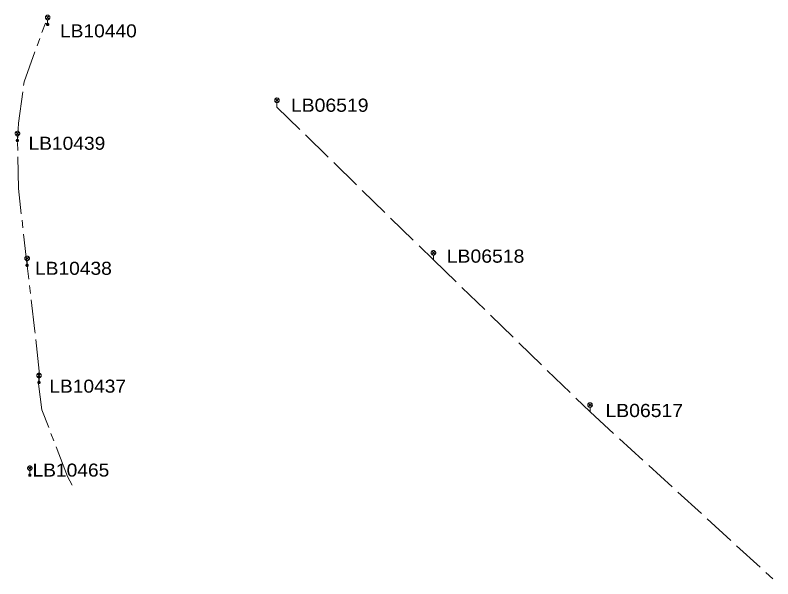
# Model space of a CAD drawing. Extents: x -691843 to -691118, y -976392 to -975793.
# Drawn here: x -691659.5 to -691534.9, y -976375.5 to -976282.7 of the extents above; entities that cross this region are included whole.
import ezdxf

# ---------------------------------------------------------------- set-up
doc = ezdxf.new("R2010")
doc.units = 0
doc.header["$LTSCALE"] = 0.87
doc.linetypes.add('LONG_DASH_SHORT_DASH', pattern=[9.9, 6, -1.2, 1.5, -1.2])
doc.linetypes.add('LONG_DASHED', pattern=[7.5, 6, -1.5])
doc.layers.add('1', color=7, linetype='Continuous', lineweight=13)

msp = doc.modelspace()

# ---------------------------------------------------------------- linework, layer by layer
at = {"layer": '1'}
for p, q in [((-691654.435, -976282.845), (-691653.905, -976283.375)), ((-691654.435, -976283.375), (-691653.905, -976282.845)), ((-691654.17, -976284.26), (-691654.17, -976283.485)), ((-691616.735, -976296.475), (-691616.205, -976297.005)), ((-691616.735, -976297.005), (-691616.205, -976296.475)), ((-691616.47, -976297.89), (-691616.47, -976297.115)), ((-691659.405, -976301.945), (-691658.875, -976302.475)), ((-691659.405, -976302.475), (-691658.875, -976301.945)), ((-691659.14, -976303.36), (-691659.14, -976302.585)), ((-691591.005, -976321.575), (-691590.475, -976322.105)), ((-691591.005, -976322.105), (-691590.475, -976321.575)), ((-691657.815, -976322.475), (-691657.285, -976323.005)), ((-691657.815, -976323.005), (-691657.285, -976322.475)), ((-691590.74, -976322.99), (-691590.74, -976322.215)), ((-691657.55, -976323.89), (-691657.55, -976323.115)), ((-691655.855, -976341.755), (-691655.325, -976342.285)), ((-691655.855, -976342.285), (-691655.325, -976341.755)), ((-691655.59, -976343.17), (-691655.59, -976342.395)), ((-691565.255, -976346.605), (-691564.725, -976347.135)), ((-691565.255, -976347.135), (-691564.725, -976346.605)), ((-691564.99, -976348.02), (-691564.99, -976347.245)), ((-691657.365, -976356.995), (-691656.835, -976357.525)), ((-691657.365, -976357.525), (-691656.835, -976356.995)), ((-691657.1, -976358.41), (-691657.1, -976357.635))]:
    msp.add_line(p, q, dxfattribs=at)
at = {"layer": '1', "linetype": 'LONG_DASH_SHORT_DASH'}
for p, q in [((-691654.54, -976284.04), (-691654.17, -976284.26)), ((-691654.54, -976284.04), (-691654.17, -976284.26)), ((-691654.54, -976284.04), (-691654.17, -976284.26)), ((-691654.54, -976284.04), (-691654.17, -976284.26)), ((-691654.54, -976284.04), (-691654.17, -976284.26)), ((-691654.54, -976284.04), (-691654.17, -976284.26)), ((-691654.54, -976284.04), (-691654.17, -976284.26)), ((-691659.11, -976303.48), (-691659.14, -976303.36)), ((-691659.11, -976303.48), (-691659.14, -976303.36)), ((-691659.11, -976303.48), (-691659.14, -976303.36)), ((-691659.11, -976303.48), (-691659.14, -976303.36)), ((-691659.11, -976303.48), (-691659.14, -976303.36)), ((-691659.11, -976303.48), (-691659.14, -976303.36)), ((-691659.11, -976303.48), (-691659.14, -976303.36)), ((-691659.11, -976303.48), (-691659.14, -976303.36)), ((-691657.53, -976323.97), (-691657.55, -976323.89)), ((-691657.53, -976323.97), (-691657.55, -976323.89)), ((-691657.53, -976323.97), (-691657.55, -976323.89)), ((-691657.53, -976323.97), (-691657.55, -976323.89)), ((-691657.53, -976323.97), (-691657.55, -976323.89)), ((-691657.53, -976323.97), (-691657.55, -976323.89)), ((-691657.53, -976323.97), (-691657.55, -976323.89)), ((-691657.53, -976323.97), (-691657.55, -976323.89)), ((-691655.67, -976343.36), (-691655.59, -976343.17)), ((-691655.67, -976343.36), (-691655.59, -976343.17)), ((-691655.67, -976343.36), (-691655.59, -976343.17)), ((-691655.67, -976343.36), (-691655.59, -976343.17)), ((-691655.67, -976343.36), (-691655.59, -976343.17)), ((-691655.67, -976343.36), (-691655.59, -976343.17)), ((-691655.67, -976343.36), (-691655.59, -976343.17)), ((-691655.67, -976343.36), (-691655.59, -976343.17))]:
    msp.add_line(p, q, dxfattribs=at)
at = {"layer": '1', "linetype": 'LONG_DASHED'}
for p, q in [((-691616.47, -976297.89), (-691590.74, -976322.99)), ((-691616.47, -976297.89), (-691590.74, -976322.99)), ((-691590.74, -976322.99), (-691564.99, -976348.02)), ((-691590.74, -976322.99), (-691564.99, -976348.02)), ((-691564.99, -976348.02), (-691534.94, -976375.47)), ((-691564.99, -976348.02), (-691534.94, -976375.47))]:
    msp.add_line(p, q, dxfattribs=at)
at = {"layer": '1'}
for points in [[(-691653.795, -976283.11), (-691653.801, -976283.045), (-691653.818, -976282.982), (-691653.845, -976282.923), (-691653.883, -976282.869), (-691653.929, -976282.823), (-691653.982, -976282.785), (-691654.042, -976282.758), (-691654.105, -976282.741), (-691654.17, -976282.735), (-691654.235, -976282.741), (-691654.298, -976282.758), (-691654.358, -976282.785), (-691654.411, -976282.823), (-691654.457, -976282.869), (-691654.495, -976282.923), (-691654.522, -976282.982), (-691654.539, -976283.045), (-691654.545, -976283.11), (-691654.539, -976283.175), (-691654.522, -976283.238), (-691654.495, -976283.298), (-691654.457, -976283.351), (-691654.411, -976283.397), (-691654.358, -976283.435), (-691654.298, -976283.462), (-691654.235, -976283.479), (-691654.17, -976283.485), (-691654.105, -976283.479), (-691654.042, -976283.462), (-691653.982, -976283.435), (-691653.929, -976283.397), (-691653.883, -976283.351), (-691653.845, -976283.298), (-691653.818, -976283.238), (-691653.801, -976283.175)], [(-691653.98, -976284.26), (-691653.983, -976284.227), (-691653.991, -976284.195), (-691654.005, -976284.165), (-691654.024, -976284.138), (-691654.048, -976284.114), (-691654.075, -976284.095), (-691654.105, -976284.081), (-691654.137, -976284.073), (-691654.17, -976284.07), (-691654.203, -976284.073), (-691654.235, -976284.081), (-691654.265, -976284.095), (-691654.292, -976284.114), (-691654.316, -976284.138), (-691654.335, -976284.165), (-691654.349, -976284.195), (-691654.357, -976284.227), (-691654.36, -976284.26), (-691654.357, -976284.293), (-691654.349, -976284.325), (-691654.335, -976284.355), (-691654.316, -976284.382), (-691654.292, -976284.406), (-691654.265, -976284.425), (-691654.235, -976284.439), (-691654.203, -976284.447), (-691654.17, -976284.45), (-691654.137, -976284.447), (-691654.105, -976284.439), (-691654.075, -976284.425), (-691654.048, -976284.406), (-691654.024, -976284.382), (-691654.005, -976284.355), (-691653.991, -976284.325), (-691653.983, -976284.293)], [(-691654.12, -976284.26), (-691654.121, -976284.251), (-691654.123, -976284.243), (-691654.127, -976284.235), (-691654.132, -976284.228), (-691654.138, -976284.222), (-691654.145, -976284.217), (-691654.153, -976284.213), (-691654.161, -976284.211), (-691654.17, -976284.21), (-691654.179, -976284.211), (-691654.187, -976284.213), (-691654.195, -976284.217), (-691654.202, -976284.222), (-691654.208, -976284.228), (-691654.213, -976284.235), (-691654.217, -976284.243), (-691654.219, -976284.251), (-691654.22, -976284.26), (-691654.219, -976284.269), (-691654.217, -976284.277), (-691654.213, -976284.285), (-691654.208, -976284.292), (-691654.202, -976284.298), (-691654.195, -976284.303), (-691654.187, -976284.307), (-691654.179, -976284.309), (-691654.17, -976284.31), (-691654.161, -976284.309), (-691654.153, -976284.307), (-691654.145, -976284.303), (-691654.138, -976284.298), (-691654.132, -976284.292), (-691654.127, -976284.285), (-691654.123, -976284.277), (-691654.121, -976284.269)], [(-691616.095, -976296.74), (-691616.101, -976296.675), (-691616.118, -976296.612), (-691616.145, -976296.552), (-691616.183, -976296.499), (-691616.229, -976296.453), (-691616.282, -976296.415), (-691616.342, -976296.388), (-691616.405, -976296.371), (-691616.47, -976296.365), (-691616.535, -976296.371), (-691616.598, -976296.388), (-691616.658, -976296.415), (-691616.711, -976296.453), (-691616.757, -976296.499), (-691616.795, -976296.552), (-691616.822, -976296.612), (-691616.839, -976296.675), (-691616.845, -976296.74), (-691616.839, -976296.805), (-691616.822, -976296.868), (-691616.795, -976296.928), (-691616.757, -976296.981), (-691616.711, -976297.027), (-691616.658, -976297.065), (-691616.598, -976297.092), (-691616.535, -976297.109), (-691616.47, -976297.115), (-691616.405, -976297.109), (-691616.342, -976297.092), (-691616.282, -976297.065), (-691616.229, -976297.027), (-691616.183, -976296.981), (-691616.145, -976296.928), (-691616.118, -976296.868), (-691616.101, -976296.805)], [(-691658.765, -976302.21), (-691658.771, -976302.145), (-691658.788, -976302.082), (-691658.815, -976302.022), (-691658.853, -976301.969), (-691658.899, -976301.923), (-691658.952, -976301.885), (-691659.012, -976301.858), (-691659.075, -976301.841), (-691659.14, -976301.835), (-691659.205, -976301.841), (-691659.268, -976301.858), (-691659.328, -976301.885), (-691659.381, -976301.923), (-691659.427, -976301.969), (-691659.465, -976302.022), (-691659.492, -976302.082), (-691659.509, -976302.145), (-691659.515, -976302.21), (-691659.509, -976302.275), (-691659.492, -976302.338), (-691659.465, -976302.398), (-691659.427, -976302.451), (-691659.381, -976302.497), (-691659.328, -976302.535), (-691659.268, -976302.562), (-691659.205, -976302.579), (-691659.14, -976302.585), (-691659.075, -976302.579), (-691659.012, -976302.562), (-691658.952, -976302.535), (-691658.899, -976302.497), (-691658.853, -976302.451), (-691658.815, -976302.398), (-691658.788, -976302.338), (-691658.771, -976302.275)], [(-691658.95, -976303.36), (-691658.953, -976303.327), (-691658.961, -976303.295), (-691658.975, -976303.265), (-691658.994, -976303.238), (-691659.018, -976303.214), (-691659.045, -976303.195), (-691659.075, -976303.181), (-691659.107, -976303.173), (-691659.14, -976303.17), (-691659.173, -976303.173), (-691659.205, -976303.181), (-691659.235, -976303.195), (-691659.262, -976303.214), (-691659.286, -976303.238), (-691659.305, -976303.265), (-691659.319, -976303.295), (-691659.327, -976303.327), (-691659.33, -976303.36), (-691659.327, -976303.393), (-691659.319, -976303.425), (-691659.305, -976303.455), (-691659.286, -976303.482), (-691659.262, -976303.506), (-691659.235, -976303.525), (-691659.205, -976303.539), (-691659.173, -976303.547), (-691659.14, -976303.55), (-691659.107, -976303.547), (-691659.075, -976303.539), (-691659.045, -976303.525), (-691659.018, -976303.506), (-691658.994, -976303.482), (-691658.975, -976303.455), (-691658.961, -976303.425), (-691658.953, -976303.393)], [(-691659.09, -976303.36), (-691659.091, -976303.351), (-691659.093, -976303.343), (-691659.097, -976303.335), (-691659.102, -976303.328), (-691659.108, -976303.322), (-691659.115, -976303.317), (-691659.123, -976303.313), (-691659.131, -976303.311), (-691659.14, -976303.31), (-691659.149, -976303.311), (-691659.157, -976303.313), (-691659.165, -976303.317), (-691659.172, -976303.322), (-691659.178, -976303.328), (-691659.183, -976303.335), (-691659.187, -976303.343), (-691659.189, -976303.351), (-691659.19, -976303.36), (-691659.189, -976303.369), (-691659.187, -976303.377), (-691659.183, -976303.385), (-691659.178, -976303.392), (-691659.172, -976303.398), (-691659.165, -976303.403), (-691659.157, -976303.407), (-691659.149, -976303.409), (-691659.14, -976303.41), (-691659.131, -976303.409), (-691659.123, -976303.407), (-691659.115, -976303.403), (-691659.108, -976303.398), (-691659.102, -976303.392), (-691659.097, -976303.385), (-691659.093, -976303.377), (-691659.091, -976303.369)], [(-691590.365, -976321.84), (-691590.371, -976321.775), (-691590.388, -976321.712), (-691590.415, -976321.653), (-691590.453, -976321.599), (-691590.499, -976321.553), (-691590.552, -976321.515), (-691590.612, -976321.488), (-691590.675, -976321.471), (-691590.74, -976321.465), (-691590.805, -976321.471), (-691590.868, -976321.488), (-691590.928, -976321.515), (-691590.981, -976321.553), (-691591.027, -976321.599), (-691591.065, -976321.653), (-691591.092, -976321.712), (-691591.109, -976321.775), (-691591.115, -976321.84), (-691591.109, -976321.905), (-691591.092, -976321.968), (-691591.065, -976322.028), (-691591.027, -976322.081), (-691590.981, -976322.127), (-691590.928, -976322.165), (-691590.868, -976322.192), (-691590.805, -976322.209), (-691590.74, -976322.215), (-691590.675, -976322.209), (-691590.612, -976322.192), (-691590.552, -976322.165), (-691590.499, -976322.127), (-691590.453, -976322.081), (-691590.415, -976322.028), (-691590.388, -976321.968), (-691590.371, -976321.905)], [(-691657.175, -976322.74), (-691657.181, -976322.675), (-691657.198, -976322.612), (-691657.225, -976322.552), (-691657.263, -976322.499), (-691657.309, -976322.453), (-691657.362, -976322.415), (-691657.422, -976322.388), (-691657.485, -976322.371), (-691657.55, -976322.365), (-691657.615, -976322.371), (-691657.678, -976322.388), (-691657.738, -976322.415), (-691657.791, -976322.453), (-691657.837, -976322.499), (-691657.875, -976322.552), (-691657.902, -976322.612), (-691657.919, -976322.675), (-691657.925, -976322.74), (-691657.919, -976322.805), (-691657.902, -976322.868), (-691657.875, -976322.928), (-691657.837, -976322.981), (-691657.791, -976323.027), (-691657.738, -976323.065), (-691657.678, -976323.092), (-691657.615, -976323.109), (-691657.55, -976323.115), (-691657.485, -976323.109), (-691657.422, -976323.092), (-691657.362, -976323.065), (-691657.309, -976323.027), (-691657.263, -976322.981), (-691657.225, -976322.928), (-691657.198, -976322.868), (-691657.181, -976322.805)], [(-691657.36, -976323.89), (-691657.363, -976323.857), (-691657.371, -976323.825), (-691657.385, -976323.795), (-691657.404, -976323.768), (-691657.428, -976323.744), (-691657.455, -976323.725), (-691657.485, -976323.711), (-691657.517, -976323.703), (-691657.55, -976323.7), (-691657.583, -976323.703), (-691657.615, -976323.711), (-691657.645, -976323.725), (-691657.672, -976323.744), (-691657.696, -976323.768), (-691657.715, -976323.795), (-691657.729, -976323.825), (-691657.737, -976323.857), (-691657.74, -976323.89), (-691657.737, -976323.923), (-691657.729, -976323.955), (-691657.715, -976323.985), (-691657.696, -976324.012), (-691657.672, -976324.036), (-691657.645, -976324.055), (-691657.615, -976324.069), (-691657.583, -976324.077), (-691657.55, -976324.08), (-691657.517, -976324.077), (-691657.485, -976324.069), (-691657.455, -976324.055), (-691657.428, -976324.036), (-691657.404, -976324.012), (-691657.385, -976323.985), (-691657.371, -976323.955), (-691657.363, -976323.923)], [(-691657.5, -976323.89), (-691657.501, -976323.881), (-691657.503, -976323.873), (-691657.507, -976323.865), (-691657.512, -976323.858), (-691657.518, -976323.852), (-691657.525, -976323.847), (-691657.533, -976323.843), (-691657.541, -976323.841), (-691657.55, -976323.84), (-691657.559, -976323.841), (-691657.567, -976323.843), (-691657.575, -976323.847), (-691657.582, -976323.852), (-691657.588, -976323.858), (-691657.593, -976323.865), (-691657.597, -976323.873), (-691657.599, -976323.881), (-691657.6, -976323.89), (-691657.599, -976323.899), (-691657.597, -976323.907), (-691657.593, -976323.915), (-691657.588, -976323.922), (-691657.582, -976323.928), (-691657.575, -976323.933), (-691657.567, -976323.937), (-691657.559, -976323.939), (-691657.55, -976323.94), (-691657.541, -976323.939), (-691657.533, -976323.937), (-691657.525, -976323.933), (-691657.518, -976323.928), (-691657.512, -976323.922), (-691657.507, -976323.915), (-691657.503, -976323.907), (-691657.501, -976323.899)], [(-691655.215, -976342.02), (-691655.221, -976341.955), (-691655.238, -976341.892), (-691655.265, -976341.832), (-691655.303, -976341.779), (-691655.349, -976341.733), (-691655.402, -976341.695), (-691655.462, -976341.668), (-691655.525, -976341.651), (-691655.59, -976341.645), (-691655.655, -976341.651), (-691655.718, -976341.668), (-691655.778, -976341.695), (-691655.831, -976341.733), (-691655.877, -976341.779), (-691655.915, -976341.832), (-691655.942, -976341.892), (-691655.959, -976341.955), (-691655.965, -976342.02), (-691655.959, -976342.085), (-691655.942, -976342.148), (-691655.915, -976342.208), (-691655.877, -976342.261), (-691655.831, -976342.307), (-691655.778, -976342.345), (-691655.718, -976342.372), (-691655.655, -976342.389), (-691655.59, -976342.395), (-691655.525, -976342.389), (-691655.462, -976342.372), (-691655.402, -976342.345), (-691655.349, -976342.307), (-691655.303, -976342.261), (-691655.265, -976342.208), (-691655.238, -976342.148), (-691655.221, -976342.085)], [(-691655.4, -976343.17), (-691655.403, -976343.137), (-691655.411, -976343.105), (-691655.425, -976343.075), (-691655.444, -976343.048), (-691655.468, -976343.024), (-691655.495, -976343.005), (-691655.525, -976342.991), (-691655.557, -976342.983), (-691655.59, -976342.98), (-691655.623, -976342.983), (-691655.655, -976342.991), (-691655.685, -976343.005), (-691655.712, -976343.024), (-691655.736, -976343.048), (-691655.755, -976343.075), (-691655.769, -976343.105), (-691655.777, -976343.137), (-691655.78, -976343.17), (-691655.777, -976343.203), (-691655.769, -976343.235), (-691655.755, -976343.265), (-691655.736, -976343.292), (-691655.712, -976343.316), (-691655.685, -976343.335), (-691655.655, -976343.349), (-691655.623, -976343.357), (-691655.59, -976343.36), (-691655.557, -976343.357), (-691655.525, -976343.349), (-691655.495, -976343.335), (-691655.468, -976343.316), (-691655.444, -976343.292), (-691655.425, -976343.265), (-691655.411, -976343.235), (-691655.403, -976343.203)], [(-691655.54, -976343.17), (-691655.541, -976343.161), (-691655.543, -976343.153), (-691655.547, -976343.145), (-691655.552, -976343.138), (-691655.558, -976343.132), (-691655.565, -976343.127), (-691655.573, -976343.123), (-691655.581, -976343.121), (-691655.59, -976343.12), (-691655.599, -976343.121), (-691655.607, -976343.123), (-691655.615, -976343.127), (-691655.622, -976343.132), (-691655.628, -976343.138), (-691655.633, -976343.145), (-691655.637, -976343.153), (-691655.639, -976343.161), (-691655.64, -976343.17), (-691655.639, -976343.179), (-691655.637, -976343.187), (-691655.633, -976343.195), (-691655.628, -976343.202), (-691655.622, -976343.208), (-691655.615, -976343.213), (-691655.607, -976343.217), (-691655.599, -976343.219), (-691655.59, -976343.22), (-691655.581, -976343.219), (-691655.573, -976343.217), (-691655.565, -976343.213), (-691655.558, -976343.208), (-691655.552, -976343.202), (-691655.547, -976343.195), (-691655.543, -976343.187), (-691655.541, -976343.179)], [(-691564.615, -976346.87), (-691564.621, -976346.805), (-691564.638, -976346.742), (-691564.665, -976346.682), (-691564.703, -976346.629), (-691564.749, -976346.583), (-691564.802, -976346.545), (-691564.862, -976346.518), (-691564.925, -976346.501), (-691564.99, -976346.495), (-691565.055, -976346.501), (-691565.118, -976346.518), (-691565.178, -976346.545), (-691565.231, -976346.583), (-691565.277, -976346.629), (-691565.315, -976346.682), (-691565.342, -976346.742), (-691565.359, -976346.805), (-691565.365, -976346.87), (-691565.359, -976346.935), (-691565.342, -976346.998), (-691565.315, -976347.058), (-691565.277, -976347.111), (-691565.231, -976347.157), (-691565.178, -976347.195), (-691565.118, -976347.222), (-691565.055, -976347.239), (-691564.99, -976347.245), (-691564.925, -976347.239), (-691564.862, -976347.222), (-691564.802, -976347.195), (-691564.749, -976347.157), (-691564.703, -976347.111), (-691564.665, -976347.058), (-691564.638, -976346.998), (-691564.621, -976346.935)], [(-691656.725, -976357.26), (-691656.731, -976357.195), (-691656.748, -976357.132), (-691656.775, -976357.072), (-691656.813, -976357.019), (-691656.859, -976356.973), (-691656.912, -976356.935), (-691656.972, -976356.908), (-691657.035, -976356.891), (-691657.1, -976356.885), (-691657.165, -976356.891), (-691657.228, -976356.908), (-691657.288, -976356.935), (-691657.341, -976356.973), (-691657.387, -976357.019), (-691657.425, -976357.072), (-691657.452, -976357.132), (-691657.469, -976357.195), (-691657.475, -976357.26), (-691657.469, -976357.325), (-691657.452, -976357.388), (-691657.425, -976357.448), (-691657.387, -976357.501), (-691657.341, -976357.547), (-691657.288, -976357.585), (-691657.228, -976357.612), (-691657.165, -976357.629), (-691657.1, -976357.635), (-691657.035, -976357.629), (-691656.972, -976357.612), (-691656.912, -976357.585), (-691656.859, -976357.547), (-691656.813, -976357.501), (-691656.775, -976357.448), (-691656.748, -976357.388), (-691656.731, -976357.325)], [(-691656.91, -976358.41), (-691656.913, -976358.377), (-691656.921, -976358.345), (-691656.935, -976358.315), (-691656.954, -976358.288), (-691656.978, -976358.264), (-691657.005, -976358.245), (-691657.035, -976358.231), (-691657.067, -976358.223), (-691657.1, -976358.22), (-691657.133, -976358.223), (-691657.165, -976358.231), (-691657.195, -976358.245), (-691657.222, -976358.264), (-691657.246, -976358.288), (-691657.265, -976358.315), (-691657.279, -976358.345), (-691657.287, -976358.377), (-691657.29, -976358.41), (-691657.287, -976358.443), (-691657.279, -976358.475), (-691657.265, -976358.505), (-691657.246, -976358.532), (-691657.222, -976358.556), (-691657.195, -976358.575), (-691657.165, -976358.589), (-691657.133, -976358.597), (-691657.1, -976358.6), (-691657.067, -976358.597), (-691657.035, -976358.589), (-691657.005, -976358.575), (-691656.978, -976358.556), (-691656.954, -976358.532), (-691656.935, -976358.505), (-691656.921, -976358.475), (-691656.913, -976358.443)], [(-691657.05, -976358.41), (-691657.051, -976358.401), (-691657.053, -976358.393), (-691657.057, -976358.385), (-691657.062, -976358.378), (-691657.068, -976358.372), (-691657.075, -976358.367), (-691657.083, -976358.363), (-691657.091, -976358.361), (-691657.1, -976358.36), (-691657.109, -976358.361), (-691657.117, -976358.363), (-691657.125, -976358.367), (-691657.132, -976358.372), (-691657.138, -976358.378), (-691657.143, -976358.385), (-691657.147, -976358.393), (-691657.149, -976358.401), (-691657.15, -976358.41), (-691657.149, -976358.419), (-691657.147, -976358.427), (-691657.143, -976358.435), (-691657.138, -976358.442), (-691657.132, -976358.448), (-691657.125, -976358.453), (-691657.117, -976358.457), (-691657.109, -976358.459), (-691657.1, -976358.46), (-691657.091, -976358.459), (-691657.083, -976358.457), (-691657.075, -976358.453), (-691657.068, -976358.448), (-691657.062, -976358.442), (-691657.057, -976358.435), (-691657.053, -976358.427), (-691657.051, -976358.419)]]:
    msp.add_lwpolyline(points, close=True, dxfattribs=at)
at = {"layer": '1', "linetype": 'LONG_DASH_SHORT_DASH'}
for points in [[(-691655.59, -976341.28), (-691656.28, -976334.73), (-691657.53, -976323.97), (-691658.98, -976311.25), (-691659.11, -976303.48), (-691658.99, -976300.51), (-691658.04, -976293.69), (-691654.54, -976284.04)], [(-691655.59, -976341.28), (-691656.28, -976334.73), (-691657.53, -976323.97), (-691658.98, -976311.25), (-691659.11, -976303.48), (-691658.99, -976300.51), (-691658.04, -976293.69), (-691654.54, -976284.04)], [(-691655.59, -976341.28), (-691656.28, -976334.73), (-691657.53, -976323.97), (-691658.98, -976311.25), (-691659.11, -976303.48), (-691658.99, -976300.51), (-691658.04, -976293.69), (-691654.54, -976284.04)], [(-691655.59, -976341.28), (-691656.28, -976334.73), (-691657.53, -976323.97), (-691658.98, -976311.25), (-691659.11, -976303.48), (-691658.99, -976300.51), (-691658.04, -976293.69), (-691654.54, -976284.04)], [(-691655.59, -976341.28), (-691656.28, -976334.73), (-691657.53, -976323.97), (-691658.98, -976311.25), (-691659.11, -976303.48), (-691658.99, -976300.51), (-691658.04, -976293.69), (-691654.54, -976284.04), (-691654.17, -976284.26)], [(-691655.59, -976341.28), (-691656.28, -976334.73), (-691657.53, -976323.97), (-691658.98, -976311.25), (-691659.11, -976303.48), (-691658.99, -976300.51), (-691658.04, -976293.69), (-691654.54, -976284.04)], [(-691655.59, -976341.28), (-691656.28, -976334.73), (-691657.53, -976323.97), (-691658.98, -976311.25), (-691659.11, -976303.48), (-691658.99, -976300.51), (-691658.04, -976293.69), (-691654.54, -976284.04)], [(-691655.59, -976341.28), (-691656.28, -976334.73), (-691657.53, -976323.97), (-691658.98, -976311.25), (-691659.11, -976303.48), (-691658.99, -976300.51), (-691658.04, -976293.69), (-691654.54, -976284.04)], [(-691650.14, -976360.06), (-691650.92, -976358.63), (-691655.11, -976347.68), (-691655.67, -976343.36), (-691655.59, -976341.28)], [(-691650.14, -976360.06), (-691650.92, -976358.63), (-691655.11, -976347.68), (-691655.67, -976343.36), (-691655.59, -976341.28)], [(-691650.14, -976360.06), (-691650.92, -976358.63), (-691655.11, -976347.68), (-691655.67, -976343.36), (-691655.59, -976341.28)], [(-691650.14, -976360.06), (-691650.92, -976358.63), (-691655.11, -976347.68), (-691655.67, -976343.36), (-691655.59, -976341.28)], [(-691650.14, -976360.06), (-691650.92, -976358.63), (-691655.11, -976347.68), (-691655.67, -976343.36), (-691655.59, -976341.28)], [(-691650.14, -976360.06), (-691650.92, -976358.63), (-691655.11, -976347.68), (-691655.67, -976343.36), (-691655.59, -976341.28)], [(-691650.14, -976360.06), (-691650.92, -976358.63), (-691655.11, -976347.68), (-691655.67, -976343.36), (-691655.59, -976341.28)], [(-691650.14, -976360.06), (-691650.92, -976358.63), (-691655.11, -976347.68), (-691655.67, -976343.36), (-691655.59, -976341.28)]]:
    msp.add_lwpolyline(points, dxfattribs=at)

# ---------------------------------------------------------------- texts
at = {"layer": '1', "width": 1.1}
for s, height, p in [('LB10440', 2.144, (-691652.149, -976286.391)), ('LB06519', 2.167, (-691614.176, -976298.631)), ('LB10439', 2.144, (-691657.321, -976304.882)), ('LB06518', 2.167, (-691588.553, -976323.46)), ('LB10438', 2.144, (-691656.249, -976325.452)), ('LB10437', 2.144, (-691653.904, -976344.841)), ('LB06517', 2.167, (-691562.461, -976348.855)), ('LB10465', 2.144, (-691656.661, -976358.649))]:
    msp.add_text(s, height=height, dxfattribs=at).set_placement(p)

doc.saveas('drawing.dxf')
